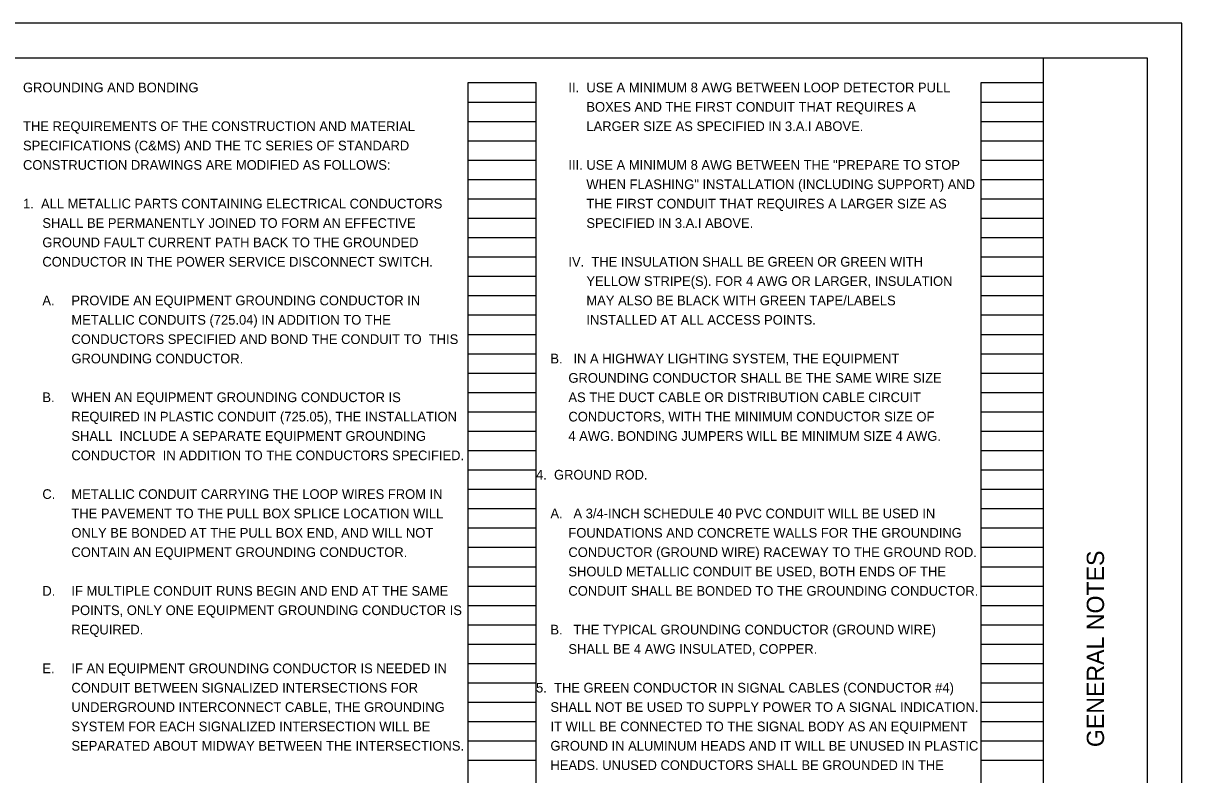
# Model space of a CAD drawing. Extents: x 0 to 34, y 0 to 22.
# Drawn here: x 17.24 to 34, y 11.13 to 22 of the extents above; entities that cross this region are included whole.
import ezdxf

# ---------------------------------------------------------------- set-up
doc = ezdxf.new("R2010")
doc.units = 0
for name, color, linetype in [('SH_Border', 7, 'Continuous'), ('SH_Cut_Line', 7, 'Continuous'), ('SH_Data', 7, 'Continuous'), ('SH_Text', 7, 'Continuous')]:
    doc.layers.add(name, color=color, linetype=linetype)

msp = doc.modelspace()

# ---------------------------------------------------------------- linework, layer by layer
at = {"layer": 'SH_Border'}
msp.add_line((32, 0.5), (32, 21.5), dxfattribs=at)
msp.add_lwpolyline([(1.5, 21.5), (33.5, 21.5), (33.5, 0.5), (1.5, 0.5)], close=True, dxfattribs=at)
at = {"layer": 'SH_Cut_Line'}
msp.add_lwpolyline([(0, 0), (34, 0), (34, 22), (0, 22)], close=True, dxfattribs=at)
at = {"layer": 'SH_Data'}
for p, q in [((23.68, 0.98), (23.68, 21.14)), ((23.68, 21.14), (24.66, 21.14)), ((24.66, 0.98), (24.66, 21.14)), ((31.1, 0.98), (31.1, 21.14)), ((31.1, 21.14), (32, 21.14)), ((32, 0.98), (32, 21.14)), ((23.68, 20.86), (24.66, 20.86)), ((31.1, 20.86), (32, 20.86)), ((23.68, 20.58), (24.66, 20.58)), ((31.1, 20.58), (32, 20.58)), ((23.68, 20.3), (24.66, 20.3)), ((31.1, 20.3), (32, 20.3)), ((23.68, 20.02), (24.66, 20.02)), ((31.1, 20.02), (32, 20.02)), ((23.68, 19.74), (24.66, 19.74)), ((31.1, 19.74), (32, 19.74)), ((23.68, 19.46), (24.66, 19.46)), ((31.1, 19.46), (32, 19.46)), ((23.68, 19.18), (24.66, 19.18)), ((31.1, 19.18), (32, 19.18)), ((23.68, 18.9), (24.66, 18.9)), ((31.1, 18.9), (32, 18.9)), ((23.68, 18.62), (24.66, 18.62)), ((31.1, 18.62), (32, 18.62)), ((23.68, 18.34), (24.66, 18.34)), ((31.1, 18.34), (32, 18.34)), ((23.68, 18.06), (24.66, 18.06)), ((31.1, 18.06), (32, 18.06)), ((23.68, 17.78), (24.66, 17.78)), ((31.1, 17.78), (32, 17.78)), ((23.68, 17.5), (24.66, 17.5)), ((31.1, 17.5), (32, 17.5)), ((23.68, 17.22), (24.66, 17.22)), ((31.1, 17.22), (32, 17.22)), ((23.68, 16.94), (24.66, 16.94)), ((31.1, 16.94), (32, 16.94)), ((23.68, 16.66), (24.66, 16.66)), ((31.1, 16.66), (32, 16.66)), ((23.68, 16.38), (24.66, 16.38)), ((31.1, 16.38), (32, 16.38)), ((23.68, 16.1), (24.66, 16.1)), ((31.1, 16.1), (32, 16.1)), ((23.68, 15.82), (24.66, 15.82)), ((31.1, 15.82), (32, 15.82)), ((23.68, 15.54), (24.66, 15.54)), ((31.1, 15.54), (32, 15.54)), ((23.68, 15.26), (24.66, 15.26)), ((31.1, 15.26), (32, 15.26)), ((23.68, 14.98), (24.66, 14.98)), ((31.1, 14.98), (32, 14.98)), ((23.68, 14.7), (24.66, 14.7)), ((31.1, 14.7), (32, 14.7)), ((23.68, 14.42), (24.66, 14.42)), ((31.1, 14.42), (32, 14.42)), ((23.68, 14.14), (24.66, 14.14)), ((31.1, 14.14), (32, 14.14)), ((23.68, 13.86), (24.66, 13.86)), ((31.1, 13.86), (32, 13.86)), ((23.68, 13.58), (24.66, 13.58)), ((31.1, 13.58), (32, 13.58)), ((23.68, 13.3), (24.66, 13.3)), ((31.1, 13.3), (32, 13.3)), ((23.68, 13.02), (24.66, 13.02)), ((31.1, 13.02), (32, 13.02)), ((23.68, 12.74), (24.66, 12.74)), ((31.1, 12.74), (32, 12.74)), ((23.68, 12.46), (24.66, 12.46)), ((31.1, 12.46), (32, 12.46)), ((23.68, 12.18), (24.66, 12.18)), ((31.1, 12.18), (32, 12.18)), ((23.68, 11.9), (24.66, 11.9)), ((31.1, 11.9), (32, 11.9)), ((23.68, 11.62), (24.66, 11.62)), ((31.1, 11.62), (32, 11.62)), ((23.68, 11.34), (24.66, 11.34)), ((31.1, 11.34), (32, 11.34))]:
    msp.add_line(p, q, dxfattribs=at)

# ---------------------------------------------------------------- texts
msp.add_text('GENERAL NOTES', height=0.25, rotation=90, dxfattribs=at).set_placement((32.875, 11.531))
at = {"layer": 'SH_Text'}
for s, p in [('GROUNDING AND BONDING', (17.24, 21)), ('         II.  USE A MINIMUM 8 AWG BETWEEN LOOP DETECTOR PULL', (24.66, 21)), ('              BOXES AND THE FIRST CONDUIT THAT REQUIRES A', (24.66, 20.72)), ('THE REQUIREMENTS OF THE CONSTRUCTION AND MATERIAL ', (17.24, 20.44)), ('              LARGER SIZE AS SPECIFIED IN 3.A.I ABOVE.', (24.66, 20.44)), ('SPECIFICATIONS (C&MS) AND THE TC SERIES OF STANDARD ', (17.24, 20.16)), ('CONSTRUCTION DRAWINGS ARE MODIFIED AS FOLLOWS:', (17.24, 19.88)), ('         III. USE A MINIMUM 8 AWG BETWEEN THE "PREPARE TO STOP', (24.66, 19.88)), ('              WHEN FLASHING" INSTALLATION (INCLUDING SUPPORT) AND ', (24.66, 19.6)), ('1.  ALL METALLIC PARTS CONTAINING ELECTRICAL CONDUCTORS  ', (17.24, 19.32)), ('              THE FIRST CONDUIT THAT REQUIRES A LARGER SIZE AS ', (24.66, 19.32)), ('SHALL BE PERMANENTLY JOINED TO FORM AN EFFECTIVE ', (17.52, 19.04)), ('              SPECIFIED IN 3.A.I ABOVE.', (24.66, 19.04)), ('GROUND FAULT CURRENT PATH BACK TO THE GROUNDED ', (17.52, 18.76)), ('CONDUCTOR IN THE POWER SERVICE DISCONNECT SWITCH.', (17.52, 18.48)), ('         IV.  THE INSULATION SHALL BE GREEN OR GREEN WITH', (24.66, 18.48)), ('              YELLOW STRIPE(S). FOR 4 AWG OR LARGER, INSULATION', (24.66, 18.2)), ('A.', (17.52, 17.92)), ('PROVIDE AN EQUIPMENT GROUNDING CONDUCTOR IN ', (17.94, 17.92)), ('              MAY ALSO BE BLACK WITH GREEN TAPE/LABELS', (24.66, 17.92)), ('METALLIC CONDUITS (725.04) IN ADDITION TO THE ', (17.94, 17.64)), ('              INSTALLED AT ALL ACCESS POINTS.', (24.66, 17.64)), ('CONDUCTORS SPECIFIED AND BOND THE CONDUIT TO  THIS ', (17.94, 17.36)), ('GROUNDING CONDUCTOR. ', (17.94, 17.08)), ('    B.   IN A HIGHWAY LIGHTING SYSTEM, THE EQUIPMENT', (24.66, 17.08)), ('         GROUNDING CONDUCTOR SHALL BE THE SAME WIRE SIZE', (24.66, 16.8)), ('B.', (17.52, 16.52)), ('WHEN AN EQUIPMENT GROUNDING CONDUCTOR IS ', (17.94, 16.52)), ('         AS THE DUCT CABLE OR DISTRIBUTION CABLE CIRCUIT', (24.66, 16.52)), ('REQUIRED IN PLASTIC CONDUIT (725.05), THE INSTALLATION  ', (17.94, 16.24)), ('         CONDUCTORS, WITH THE MINIMUM CONDUCTOR SIZE OF', (24.66, 16.24)), ('SHALL  INCLUDE A SEPARATE EQUIPMENT GROUNDING  ', (17.94, 15.96)), ('         4 AWG. BONDING JUMPERS WILL BE MINIMUM SIZE 4 AWG.', (24.66, 15.96)), ('CONDUCTOR  IN ADDITION TO THE CONDUCTORS SPECIFIED.', (17.94, 15.68)), ('4.  GROUND ROD.', (24.66, 15.4)), ('C.', (17.52, 15.12)), ('METALLIC CONDUIT CARRYING THE LOOP WIRES FROM IN ', (17.94, 15.12)), ('THE PAVEMENT TO THE PULL BOX SPLICE LOCATION WILL ', (17.94, 14.84)), ('    A.   A 3/4-INCH SCHEDULE 40 PVC CONDUIT WILL BE USED IN', (24.66, 14.84)), ('ONLY BE BONDED AT THE PULL BOX END, AND WILL NOT ', (17.94, 14.56)), ('         FOUNDATIONS AND CONCRETE WALLS FOR THE GROUNDING', (24.66, 14.56)), ('CONTAIN AN EQUIPMENT GROUNDING CONDUCTOR.', (17.94, 14.28)), ('         CONDUCTOR (GROUND WIRE) RACEWAY TO THE GROUND ROD. ', (24.66, 14.28)), ('         SHOULD METALLIC CONDUIT BE USED, BOTH ENDS OF THE ', (24.66, 14)), ('D.', (17.52, 13.72)), ('IF MULTIPLE CONDUIT RUNS BEGIN AND END AT THE SAME ', (17.94, 13.72)), ('         CONDUIT SHALL BE BONDED TO THE GROUNDING CONDUCTOR.', (24.66, 13.72)), ('POINTS, ONLY ONE EQUIPMENT GROUNDING CONDUCTOR IS ', (17.94, 13.44)), ('REQUIRED.', (17.94, 13.16)), ('    B.   THE TYPICAL GROUNDING CONDUCTOR (GROUND WIRE)', (24.66, 13.16)), ('         SHALL BE 4 AWG INSULATED, COPPER.', (24.66, 12.88)), ('E.', (17.52, 12.6)), ('IF AN EQUIPMENT GROUNDING CONDUCTOR IS NEEDED IN ', (17.94, 12.6)), ('CONDUIT BETWEEN SIGNALIZED INTERSECTIONS FOR ', (17.94, 12.32)), ('5.  THE GREEN CONDUCTOR IN SIGNAL CABLES (CONDUCTOR #4)', (24.66, 12.32)), ('UNDERGROUND INTERCONNECT CABLE, THE GROUNDING ', (17.94, 12.04)), ('    SHALL NOT BE USED TO SUPPLY POWER TO A SIGNAL INDICATION. ', (24.66, 12.04)), ('SYSTEM FOR EACH SIGNALIZED INTERSECTION WILL BE ', (17.94, 11.76)), ('    IT WILL BE CONNECTED TO THE SIGNAL BODY AS AN EQUIPMENT ', (24.66, 11.76)), ('SEPARATED ABOUT MIDWAY BETWEEN THE INTERSECTIONS.', (17.94, 11.48)), ('    GROUND IN ALUMINUM HEADS AND IT WILL BE UNUSED IN PLASTIC ', (24.66, 11.48)), ('    HEADS. UNUSED CONDUCTORS SHALL BE GROUNDED IN THE ', (24.66, 11.2))]:
    msp.add_text(s, height=0.14, dxfattribs=at).set_placement(p)

doc.saveas('drawing.dxf')
